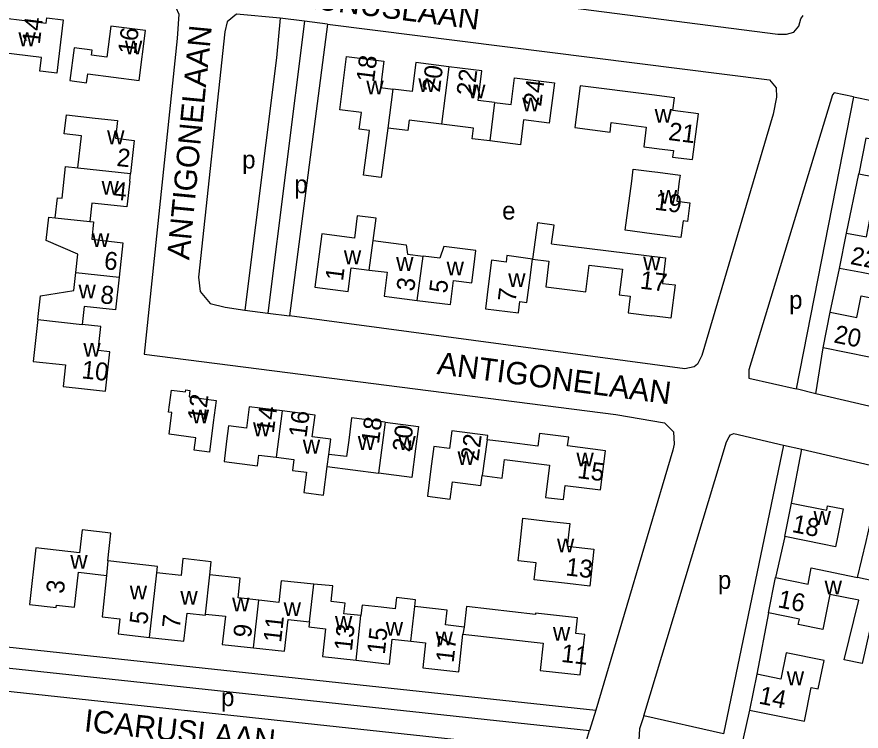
# Model space of a CAD drawing. Extents: x 161773 to 163836, y 384796 to 386521.
# Drawn here: x 162358.6 to 162546.6, y 385877.5 to 386036.6 of the extents above; entities that cross this region are included whole.
import ezdxf

# ---------------------------------------------------------------- set-up
doc = ezdxf.new("R2010")
doc.units = 0
for name, color, linetype in [('BLT_Basislijn', 7, 'Continuous'), ('BLT_Bebouwing', 7, 'Continuous'), ('BLT_Centroide', 7, 'Continuous'), ('BLT_Huisnummer', 7, 'Continuous'), ('BLT_Onderverdeling_panden', 7, 'Continuous'), ('BLT_Straatnaam', 7, 'Continuous')]:
    doc.layers.add(name, color=color, linetype=linetype)

msp = doc.modelspace()

# ---------------------------------------------------------------- linework, layer by layer
at = {"layer": 'BLT_Basislijn'}
for p, q in [((162422.66, 386035.65), (162417.24, 386036.35)), ((162422.66, 386035.65), (162414.5, 385970.61)), ((162427.79, 386035), (162419.3, 385969.99)), ((162427.79, 386035), (162422.66, 386035.65)), ((162544.97, 386018.84), (162532.13, 385953.71)), ((162544.97, 386018.84), (162549.28, 386017.9)), ((162543.34, 385988.46), (162546.11, 386001.65)), ((162539.77, 385970.83), (162541.79, 385980.59)), ((162409.35, 385971.29), (162414.5, 385970.61)), ((162414.5, 385970.61), (162419.3, 385969.99)), ((162536.53, 385952.66), (162538.17, 385962.85)), ((162536.53, 385952.66), (162532.13, 385953.71)), ((162529.37, 385941.22), (162533.46, 385940.28)), ((162531.11, 385928.25), (162533.46, 385940.28)), ((162529.62, 385920.81), (162527.54, 385911.67)), ((162525.99, 385903.8), (162523.37, 385890.14)), ((162313.11, 385900.9), (162487.53, 385882.12)), ((162312.67, 385896.24), (162486.1, 385877.57)), ((162487.53, 385882.12), (162486.1, 385877.57))]:
    msp.add_line(p, q, dxfattribs=at)
for points in [[(162313.11, 385900.9), (162324.65, 386003.69), (162328.7, 386042.76), (162329.67, 386045.91), (162331.52, 386047.14), (162336.37, 386046.82), (162391.99, 386040.11), (162393.98, 386038.7), (162394.67, 386037.26), (162394.3, 386031.81), (162386.9, 385961.46), (162492, 385948), (162502.84, 385946.15), (162504.84, 385944.19), (162504.96, 385941.44), (162504.67, 385940.04), (162487.53, 385882.12)], [(162414.95, 386047.44), (162528.09, 386032.81), (162530, 386032.76), (162531.63, 386033.24), (162532.77, 386034.59), (162533.22, 386036.2), (162533.72, 386036.93)], [(162417.24, 386036.35), (162407.49, 386037.27), (162405.43, 386035.56), (162404.93, 386033.28), (162399.04, 385978.59), (162399.42, 385975.42), (162401.61, 385972.72), (162404.97, 385971.93), (162409.35, 385971.29)], [(162417.24, 386036.35), (162416.39, 386027.54), (162409.35, 385971.29)], [(162427.79, 386035), (162526.23, 386022.61), (162527.72, 386020.79), (162527.78, 386018.72), (162527.07, 386014.94), (162511.15, 385961.14), (162510.16, 385959.27), (162509.46, 385958.63), (162507.34, 385958.22), (162419.3, 385969.99)], [(162544.97, 386018.84), (162540.61, 386019.71), (162540.26, 386019.23), (162521.65, 385957.96), (162521.62, 385956.1), (162532.13, 385953.71)], [(162549.28, 386017.9), (162600, 386006.22), (162752.16, 385971.19), (162781.03, 385964.3), (162782.71, 385962.66), (162783.02, 385959.97), (162753.01, 385905.28), (162751.78, 385904.02), (162750.54, 385903.44), (162748.49, 385903.14), (162600, 385937.83), (162536.53, 385952.66)], [(162498.2, 385880.88), (162516.68, 385941.92), (162517.26, 385943.06), (162517.5, 385943.48), (162518.29, 385943.76), (162529.37, 385941.22)], [(162529.37, 385941.22), (162515.97, 385876.86), (162498.2, 385880.88)], [(162533.46, 385940.28), (162600, 385924.77), (162684.08, 385905.17), (162740.53, 385892.3), (162742.38, 385890.58), (162742.44, 385887.3), (162711.04, 385830.23)], [(162312.67, 385896.24), (162312.77, 385894.67), (162313.69, 385892.54), (162317.19, 385890.56), (162477.99, 385873.28), (162483.44, 385873.42), (162485.48, 385875.36), (162486.1, 385877.57)], [(162521.74, 385882.16), (162520.32, 385875.52), (162600, 385856.24), (162711.04, 385830.23)], [(162498.2, 385880.88), (162497.24, 385877.94), (162497.15, 385875.44)]]:
    msp.add_lwpolyline(points, dxfattribs=at)
at = {"layer": 'BLT_Bebouwing'}
for p, q in [((162547.68, 386009.59), (162546.11, 386001.65)), ((162383.72, 386000), (162383.91, 386001.73)), ((162367.13, 385991.85), (162374.8, 385991.02)), ((162374.8, 385991.02), (162375.67, 385990.92)), ((162541.79, 385980.59), (162543.34, 385988.46)), ((162472.81, 385977.94), (162473.47, 385982.65)), ((162538.17, 385962.85), (162539.77, 385970.83)), ((162402.97, 385951.17), (162402.33, 385946.21)), ((162427.72, 385936.42), (162439.1, 385934.93)), ((162529.62, 385920.81), (162531.11, 385928.25)), ((162401.88, 385915.21), (162395.58, 385915.92)), ((162401.54, 385912.28), (162401.88, 385915.21)), ((162534.82, 385910.23), (162535.53, 385913.82)), ((162535.53, 385913.82), (162545.85, 385911.66)), ((162525.99, 385903.8), (162527.54, 385911.67)), ((162527.54, 385911.67), (162534.82, 385910.23)), ((162539.63, 385907.89), (162538.1, 385900.12)), ((162546.12, 385906.61), (162539.63, 385907.89)), ((162532.88, 385902.44), (162525.99, 385903.8)), ((162532.64, 385901.2), (162532.88, 385902.44)), ((162538.1, 385900.12), (162532.64, 385901.2)), ((162523.37, 385890.14), (162521.74, 385882.16))]:
    msp.add_line(p, q, dxfattribs=at)
for points in [[(162350.56, 386036.98), (162365.09, 386035.2), (162365.24, 386036.42), (162368.92, 386035.96), (162368.31, 386031)], [(162385.83, 386022.49), (162387.24, 386033.59), (162379.54, 386034.57), (162378.65, 386027.63), (162375.17, 386028.08), (162375.32, 386029.23), (162371.31, 386029.74), (162370.38, 386022.44), (162374.11, 386021.96), (162374.37, 386023.95), (162385.83, 386022.49)], [(162368.31, 386031), (162367.46, 386024.09), (162364.47, 386024.45), (162363.7, 386024.55), (162364.07, 386027.59), (162354.93, 386028.71), (162354.52, 386025.4), (162351.94, 386023.33), (162350, 386025.76), (162349.13, 386025.87)], [(162441.19, 386011.84), (162439.76, 386000.87), (162435.81, 386001.39), (162437.11, 386011.32), (162434.83, 386011.61), (162435.31, 386015.29), (162430.53, 386015.89), (162432.03, 386027.84), (162440.32, 386026.8), (162439.58, 386020.87), (162442.33, 386020.52)], [(162454.8, 386025.51), (162447.46, 386026.43), (162446.65, 386019.98), (162442.33, 386020.52)], [(162464.99, 386017.57), (162461.32, 386018.02), (162462.15, 386024.59), (162454.8, 386025.51)], [(162464.99, 386017.57), (162468.65, 386017.11), (162469.4, 386023.07), (162478.31, 386021.96), (162477.18, 386012.97), (162471.45, 386013.68), (162470.76, 386008.13), (162463.91, 386008.99)], [(162500, 386007.46), (162501.61, 386007.26), (162504.81, 386006.85), (162504.62, 386005.39), (162509.09, 386004.83), (162510.38, 386015.02), (162504.72, 386015.74), (162505.08, 386018.59), (162500, 386019.24), (162484.05, 386021.27), (162482.87, 386011.97), (162490.72, 386010.97), (162490.99, 386013.07), (162498.75, 386012.08), (162498.2, 386007.69), (162500, 386007.46)], [(162372.16, 386002.99), (162372.95, 386010.13), (162369.14, 386010.54), (162369.6, 386014.78), (162376.04, 386014.08), (162381.01, 386013.53), (162380.58, 386009.58), (162384.72, 386009.12), (162383.91, 386001.73)], [(162453.2, 386012.75), (162445.97, 386013.65), (162445.67, 386011.28), (162441.19, 386011.84)], [(162463.91, 386008.99), (162460.01, 386009.47), (162460.31, 386011.86), (162453.2, 386012.75)], [(162546.11, 386001.65), (162552.58, 386000.37), (162552.5, 386000), (162552.32, 385999.05), (162557.01, 385998.13), (162557.38, 386000), (162557.97, 386003.02), (162556.04, 386003.4), (162556.9, 386007.77), (162547.68, 386009.59)], [(162368.65, 385996.2), (162369.42, 386003.29), (162372.16, 386002.99)], [(162495.53, 386000), (162495.88, 386002.71), (162500, 386002.17), (162501.34, 386002), (162506.3, 386001.36), (162506.12, 386000), (162505.55, 385995.57), (162508.49, 385995.19), (162507.95, 385991.05), (162506.99, 385991.18), (162506.51, 385987.47), (162500, 385988.31)], [(162383.72, 386000), (162383.09, 385994.29), (162375.25, 385995.14), (162374.8, 385991.02)], [(162494.11, 385989.07), (162495.53, 386000)], [(162367.13, 385991.85), (162367.62, 385996.31), (162368.65, 385996.2)], [(162543.34, 385988.46), (162547.82, 385987.59), (162548.97, 385993.44), (162553.88, 385992.48), (162557.04, 385991.86), (162556.23, 385987.7), (162554.52, 385988.03), (162552.65, 385978.47), (162546.7, 385979.63), (162541.79, 385980.59)], [(162371.74, 385979.7), (162372.18, 385983.77), (162365.13, 385986.79), (162365.71, 385992.01), (162367.13, 385991.85)], [(162437.93, 385986.81), (162438.58, 385991.76), (162434.4, 385992.3), (162433.77, 385987.34), (162426.49, 385988.28), (162424.96, 385976.38), (162432.38, 385975.42), (162433.06, 385980.74), (162437.07, 385980.22)], [(162375.67, 385990.92), (162375.25, 385987.07), (162382.21, 385986.3), (162381.37, 385978.65)], [(162477.7, 385986.08), (162478.26, 385990.25), (162474.55, 385990.74), (162473.47, 385982.65)], [(162500, 385988.31), (162494.11, 385989.07)], [(162437.93, 385986.81), (162445.29, 385985.86), (162445.56, 385983.78), (162449.05, 385983.33)], [(162447.78, 385973.46), (162455.16, 385972.51), (162455.86, 385977.9), (162459.89, 385977.38), (162460.34, 385980.88), (162460.81, 385984.57), (162453.65, 385985.49), (162452.82, 385982.85), (162449.05, 385983.33)], [(162477.7, 385986.08), (162503.07, 385982.95), (162502.36, 385977.24), (162505.2, 385976.89), (162504.28, 385969.48), (162500, 385970)], [(162473.47, 385982.65), (162467.73, 385983.42), (162467.54, 385981.97), (162464.33, 385982.38), (162463.59, 385976.55), (162462.96, 385971.59), (162470.33, 385970.66), (162470.64, 385973.17), (162472.19, 385972.98), (162472.81, 385977.94)], [(162473.47, 385982.65), (162477.09, 385982.17), (162476.38, 385976.44), (162485.32, 385975.34), (162486.05, 385981.33), (162493.48, 385980.41), (162492.77, 385974.71), (162495.21, 385974.41), (162494.75, 385970.65), (162500, 385970)], [(162437.07, 385980.22), (162441.08, 385979.71), (162440.39, 385974.41), (162447.78, 385973.46)], [(162363.24, 385969.19), (162363.82, 385974.49), (162371.29, 385975.64), (162371.74, 385979.7)], [(162381.37, 385978.65), (162380.57, 385971.33), (162373.59, 385972.1), (162373.15, 385968.09)], [(162539.77, 385970.83), (162545.68, 385969.64), (162546.66, 385974.5), (162556.9, 385972.44), (162555.9, 385967.46), (162551.59, 385968.33), (162550.86, 385964.67), (162549.28, 385964.99), (162548.44, 385960.79), (162538.17, 385962.85)], [(162363.24, 385969.19), (162362.22, 385959.85), (162369.41, 385959.06), (162368.88, 385954.23), (162373.67, 385953.71), (162378.31, 385953.2), (162379.27, 385962), (162376.66, 385962.28), (162377.25, 385967.64), (162373.15, 385968.09)], [(162402.33, 385946.21), (162401.47, 385939.6), (162398.05, 385940.04), (162398.41, 385942.84), (162392.47, 385943.62), (162393.1, 385948.43), (162392.39, 385948.52), (162393.03, 385953.44), (162396.14, 385953.04), (162396.2, 385953.52), (162397.12, 385953.4), (162396.93, 385951.96), (162402.97, 385951.17)], [(162417.66, 385948.81), (162410.33, 385949.75), (162409.72, 385945), (162405.74, 385945.51), (162405.3, 385942.07), (162404.72, 385937.56), (162412.21, 385936.6), (162412.51, 385938.97), (162416.33, 385938.48)], [(162428.07, 385939.14), (162428.51, 385942.54), (162424.37, 385943.07), (162424.99, 385947.87), (162417.66, 385948.81)], [(162440.58, 385946.3), (162433.13, 385947.28), (162432.49, 385942.32), (162432.01, 385938.64), (162428.07, 385939.14)], [(162440.58, 385946.3), (162448.03, 385945.33), (162447.38, 385940.37), (162446.54, 385933.96), (162439.1, 385934.93)], [(162463.34, 385942.39), (162463.46, 385943.34), (162455.45, 385944.37), (162454.94, 385940.44), (162451.46, 385940.89), (162450.82, 385935.93), (162450.02, 385929.79), (162455.07, 385929.14), (162455.58, 385933.02), (162461.9, 385932.2), (162462.19, 385934.44)], [(162474.63, 385940.93), (162467.71, 385941.82), (162463.34, 385942.39)], [(162477.25, 385936.74), (162476.34, 385929.54), (162480.32, 385929.04), (162480.72, 385932.22), (162488.56, 385931.22), (162489.67, 385939.93), (162481.25, 385941), (162481.5, 385942.99), (162475, 385943.81), (162474.63, 385940.93)], [(162416.33, 385938.48), (162420.3, 385937.97), (162419.99, 385935.55), (162423.11, 385935.15), (162422.53, 385930.61), (162426.91, 385930.05), (162427.72, 385936.42)], [(162462.19, 385934.44), (162466.68, 385933.86), (162467.21, 385938.01), (162477.25, 385936.74)], [(162531.11, 385928.25), (162538.97, 385926.68), (162539.16, 385927.65), (162542.63, 385926.96), (162541.37, 385920.65), (162540.95, 385918.54), (162538.06, 385919.12), (162529.62, 385920.81)], [(162476.75, 385924.26), (162481.72, 385923.7), (162481.15, 385918.65), (162487.09, 385917.97), (162486.17, 385909.76), (162481.2, 385910.32), (162473.78, 385911.15), (162474.22, 385914.99), (162470.21, 385915.44), (162470.65, 385919.28), (162471.28, 385924.88), (162476.75, 385924.26)], [(162545.85, 385911.66), (162547.72, 385919.72), (162548.85, 385924.59), (162553.84, 385923.44), (162553.37, 385921.44)], [(162378.85, 385915.4), (162379.54, 385921.6), (162373.1, 385922.32), (162372.53, 385917.22), (162362.79, 385918.31), (162361.38, 385905.64), (162367.37, 385904.97), (162367.44, 385905.54), (162371.43, 385905.1), (162372.3, 385912.87), (162378.58, 385912.16)], [(162395.58, 385915.92), (162395.15, 385912.1), (162389.73, 385912.71)], [(162389.73, 385912.71), (162389.9, 385914.17), (162378.85, 385915.4)], [(162378.58, 385912.16), (162377.55, 385902.92), (162381.49, 385902.48), (162381.12, 385899.11), (162388.12, 385898.33)], [(162412.46, 385906.64), (162407.85, 385907.15), (162408.34, 385911.52), (162401.54, 385912.28)], [(162424.71, 385910.23), (162417.46, 385910.97), (162416.92, 385906.14), (162412.46, 385906.64)], [(162435.23, 385903.19), (162431.43, 385903.62), (162431.7, 385906), (162428.56, 385906.35), (162428.94, 385909.8), (162424.71, 385910.23)], [(162550.8, 385910.03), (162546.87, 385892.49), (162542.84, 385893.32), (162546.12, 385906.61)], [(162447.21, 385905.22), (162447.38, 385906.72), (162443.14, 385907.2), (162442.87, 385904.74), (162439.73, 385905.09), (162435.5, 385905.56), (162435.23, 385903.19)], [(162458.23, 385900.63), (162454.02, 385901.11), (162454.39, 385904.41), (162447.21, 385905.22)], [(162474.07, 385903.48), (162458.74, 385905.2), (162458.23, 385900.63)], [(162388.12, 385898.33), (162395.8, 385897.47), (162396.51, 385903.74), (162400.56, 385903.28), (162400.59, 385903.55)], [(162400.59, 385903.55), (162405.03, 385903.05), (162404.33, 385896.79), (162411.28, 385896.01)], [(162474.11, 385903.77), (162474.07, 385903.48)], [(162475.8, 385897.07), (162475.11, 385891), (162484.06, 385889.98), (162485.09, 385899.01), (162483.07, 385899.24), (162483.46, 385902.71), (162474.11, 385903.77)], [(162411.28, 385896.01), (162418.23, 385895.24), (162419.02, 385902.31), (162423.76, 385901.78)], [(162423.76, 385901.78), (162423.64, 385900.69), (162427.36, 385900.27), (162426.67, 385894.08), (162434.12, 385893.24)], [(162446.34, 385897.47), (162449.62, 385897.1), (162449, 385891.56), (162457.01, 385890.67), (162457.95, 385899.07)], [(162457.95, 385899.07), (162475.8, 385897.07)], [(162434.12, 385893.24), (162441.57, 385892.41), (162442.19, 385897.93), (162446.34, 385897.47)], [(162521.74, 385882.16), (162534.01, 385879.66), (162535.54, 385887.16), (162537.09, 385886.85), (162538.39, 385893.21), (162529.92, 385894.93), (162528.72, 385889.05), (162523.37, 385890.14)]]:
    msp.add_lwpolyline(points, dxfattribs=at)
at = {"layer": 'BLT_Onderverdeling_panden'}
for p, q in [((162454.8, 386025.51), (162453.2, 386012.75)), ((162442.33, 386020.52), (162441.19, 386011.84)), ((162464.99, 386017.57), (162463.91, 386008.99)), ((162372.16, 386002.99), (162383.91, 386001.73)), ((162437.07, 385980.22), (162437.93, 385986.81)), ((162447.78, 385973.46), (162449.05, 385983.33)), ((162371.74, 385979.7), (162381.37, 385978.65)), ((162363.24, 385969.19), (162373.15, 385968.09)), ((162417.66, 385948.81), (162416.33, 385938.48)), ((162440.58, 385946.3), (162439.1, 385934.93)), ((162463.34, 385942.39), (162462.19, 385934.44)), ((162427.72, 385936.42), (162428.07, 385939.14)), ((162378.85, 385915.4), (162378.58, 385912.16)), ((162388.12, 385898.33), (162389.73, 385912.71)), ((162423.76, 385901.78), (162424.71, 385910.23)), ((162550.93, 385910.6), (162545.85, 385911.66)), ((162411.28, 385896.01), (162412.46, 385906.64)), ((162446.34, 385897.47), (162447.21, 385905.22)), ((162434.12, 385893.24), (162435.23, 385903.19)), ((162458.23, 385900.63), (162457.95, 385899.07))]:
    msp.add_line(p, q, dxfattribs=at)
msp.add_lwpolyline([(162400.59, 385903.55), (162401.54, 385912.28)], dxfattribs=at)

# ---------------------------------------------------------------- texts
at = {"layer": 'BLT_Centroide'}
for s, p in [('w', (162358.94, 386030.09)), ('w', (162382.65, 386028.25)), ('w', (162436.42, 386019.34)), ('w', (162448, 386019.88)), ('w', (162459.09, 386018.48)), ('w', (162471.12, 386015.59)), ('w', (162500.65, 386013.03)), ('w', (162378.68, 386008.25)), ('p', (162408.77, 386002.84)), ('p', (162420.4, 385997.33)), ('w', (162377.45, 385997)), ('w', (162501.8, 385995)), ('e', (162466.67, 385991.46)), ('w', (162375.33, 385985.34)), ('w', (162431.42, 385981.52)), ('w', (162443.06, 385980.03)), ('w', (162454.3, 385979.02)), ('w', (162498.08, 385980.12)), ('w', (162468.02, 385976.42)), ('w', (162372.31, 385973.91)), ('p', (162530.6, 385971.58)), ('w', (162373.39, 385960.91)), ('w', (162397.54, 385946.03)), ('w', (162411.19, 385943.17)), ('w', (162422.27, 385939.31)), ('w', (162434.52, 385940.12)), ('w', (162443.56, 385940.12)), ('w', (162456.73, 385936.75)), ('w', (162483.22, 385936.44)), ('w', (162536.03, 385923.41)), ('w', (162478.88, 385917.31)), ('w', (162370.48, 385913.66)), ('p', (162514.73, 385909.15)), ('w', (162538.5, 385907.91)), ('w', (162383.72, 385906.83)), ('w', (162395, 385905.61)), ('w', (162406.53, 385904.12)), ('w', (162418, 385903.08)), ('w', (162429.44, 385900.02)), ('w', (162440.75, 385898.73)), ('w', (162451.84, 385896.58)), ('w', (162477.98, 385897.59)), ('w', (162530.06, 385887.69)), ('p', (162404.07, 385883.03))]:
    msp.add_text(s, height=4, dxfattribs=at).set_placement(p)
at = {"layer": 'BLT_Huisnummer'}
for s, rotation, p in [('14', 82.9688, (162363.68, 386030.42)), ('16', 82.7314, (162385.02, 386028.12)), ('18', 82.8677, (162438.12, 386021.93)), ('20', 82.8661, (162452.78, 386019.71)), ('22', 82.862, (162460.43, 386018.86)), ('24', 82.8609, (162475.35, 386016.56)), ('21', 352.7597, (162503.56, 386009.21)), ('2', 353.7594, (162380.68, 386003.43)), ('4', 353.7592, (162379.92, 385995.99)), ('19', 352.6239, (162500.5, 385993.69)), ('6', 353.7577, (162377.87, 385980.43)), ('22', 348.9305, (162544.05, 385981.58)), ('1', 82.6733, (162431.21, 385977.65)), ('17', 352.9637, (162497.24, 385976.1)), ('3', 82.6773, (162447.05, 385975.33)), ('5', 82.7968, (162454.35, 385974.91)), ('8', 353.7597, (162377.03, 385972.85)), ('7', 82.7968, (162469.65, 385972.96)), ('20', 348.6332, (162540.36, 385964.09)), ('10', 353.7544, (162372.86, 385956.11)), ('12', 82.5765, (162400.51, 385946.41)), ('14', 82.6962, (162415.8, 385943.72)), ('16', 82.698, (162423.07, 385942.72)), ('18', 82.5576, (162439.21, 385941.32)), ('20', 82.6116, (162446.14, 385939.52)), ('22', 82.622, (162461.38, 385937.53)), ('15', 352.7833, (162483.29, 385933.87)), ('18', 348.6657, (162531.06, 385921.86)), ('13', 353.5682, (162480.69, 385912.18)), ('3', 83.6177, (162369.03, 385907.97)), ('16', 348.8324, (162527.88, 385905.09)), ('5', 83.6133, (162387.62, 385901.08)), ('7', 83.6096, (162394.86, 385900.22)), ('11', 83.6175, (162417.43, 385897.07)), ('9', 83.6145, (162410.72, 385898.14)), ('13', 83.6144, (162433.19, 385895.18)), ('15', 83.6149, (162440.52, 385894.44)), ('17', 83.4838, (162455.85, 385892.59)), ('11', 353.4813, (162479.69, 385892.9)), ('14', 348.4853, (162523.65, 385883.63))]:
    msp.add_text(s, height=4, rotation=rotation, dxfattribs=at).set_placement(p)
at = {"layer": 'BLT_Straatnaam'}
for s, height, rotation, p in [('FAUNUSLAAN', 5, 352.7513, (162416.75, 386039.42)), ('ANTIGONELAAN', 4.9999, 84.4688, (162396.97, 385982.36)), ('ANTIGONELAAN', 5, 352.5793, (162452.01, 385957.05)), ('ICARUSLAAN', 5, 353.7717, (162373.42, 385877.41))]:
    msp.add_text(s, height=height, rotation=rotation, dxfattribs=at).set_placement(p)

doc.saveas('drawing.dxf')
